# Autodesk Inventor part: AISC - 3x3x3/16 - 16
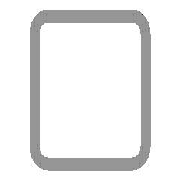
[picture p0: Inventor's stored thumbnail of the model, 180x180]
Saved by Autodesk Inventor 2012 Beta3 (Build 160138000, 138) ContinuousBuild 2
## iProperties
_CCFamilyMember: 9
_CCFamilyDisplayName: ANSI AISC (Square) - Tube
_FrameMemberDoc: Frame Member File
_Version: 15.0.0
_GetPNFromCC: 1
Created: 2010-11
Part Number: AISC - 3x3x3/16 - 16
Material: Steel, Mild
Description: Tube
Document SubType Name: Modeling
Standard: ANSI
Designer: Beta-8540w
Standards Organization: ANSI
Language: en-US
Size Designation: 3x3x3/16
Categories: <MemberInstance><Categories><Category DisplayName="Structural Shapes" InternalName="089c4875-fa83-4c05-b084-43b9cc11f5ed" Mnemonic="GRDR"><CategoryParameter Dis
Stock Number: 3x3x3/16
Density: 7.86 g/cm^3
IsCustomPart: 1
G_L: 16.000 in
G_W: 3.000 in
G_H: 3.000 in
Author: Beta-8540w
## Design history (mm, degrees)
node "Start plane"
node "End plane"
sketch "Sketch"
  geometry: L1 (-38.1, -28.575)-(-38.1, 28.575); L2 (-28.575, 38.1)-(28.575, 38.1); L3 (38.1, 28.575)-(38.1, -28.575); L4 (28.575, -38.1)-(-28.575, -38.1); L5 (-28.575, 33.337)-(28.575, 33.338); L6 (33.338, 28.575)-(33.338, -28.575); L7 (28.575, -33.337)-(-28.575, -33.338); L8 (-33.338, -28.575)-(-33.338, 28.575); L9 (0, 56.102)-(0, -56.102) reference; L10 (-56.102, 0)-(56.102, 0) reference; A1 r 9.525 centre (-28.575, -28.575) between (-38.1, -28.575) and (-28.575, -38.1); A2 r 9.525 centre (-28.575, 28.575) between (-28.575, 38.1) and (-38.1, 28.575); A3 r 9.525 centre (28.575, 28.575) between (38.1, 28.575) and (28.575, 38.1); A4 r 9.525 centre (28.575, -28.575) between (28.575, -38.1) and (38.1, -28.575); A5 r 4.763 centre (-28.575, 28.575) between (-28.575, 33.337) and (-33.338, 28.575); A6 r 4.763 centre (28.575, 28.575) between (33.338, 28.575) and (28.575, 33.338); A7 r 4.763 centre (28.575, -28.575) between (28.575, -33.337) and (33.338, -28.575); A8 r 4.763 centre (-28.575, -28.575) between (-33.338, -28.575) and (-28.575, -33.338)
  constraints: 16 end point, 16 point on circle, 8 centre point, 8 tangent, 4 parallel, 3 equal radius, 2 perpendicular, 7 other
  dimensions: "d10" = 76.2 distance between parallel lines of L2 L4 (= G_H); "d11" = 76.2 distance between parallel lines of L1 L3 (= G_W); "d12" = 4.7625 distance between parallel lines of L3 L6 (= G_T); "d15" = 38.1 distance between parallel lines of L2 L10 (= 0.5 x d10); "d16" = 38.1 distance between parallel lines of L9 L3 (= 0.5 x d11); "d17" = 9.525 radius of A1 (= G_IR)
extrude "Body" new body sketch "Sketch" stored distance "d3" = 406.4 (= G_L); taper "d4" = 0 deg
node "Driven Length"
  sketch "Sketch3"
    geometry: L1 (0, 0)-(10, 0) reference
    constraints: 2 end point, 1 horizontal
  workplane "Work Plane3"
  sketch "Sketch4"
    geometry: L1 (-2, -114.3)-(12, -114.3) reference; L2 (-2, 292.1)-(12, 292.1) reference
    dimensions: "d19" = 406.4 distance between parallel lines of L1 L2 (derived)
workplane "Work Plane4"
split "Split1"
body "Solid1"
other parameters: "G_W" = 76.2 [user parameter; used in 1 equation term], "G_H" = 76.2 [user parameter; used in 1 equation term], "G_T" = 4.7625 [user parameter; used in 1 equation term], "G_IR" = 9.525 [user parameter; used in 1 equation term], "G_L" = 406.4 (= d19) [user parameter; used in 1 equation term], "G_OFFSET_START" = 114.3 [user parameter; used in 1 equation term], "G_OFFSET_END" = 38.1 [user parameter; used in 1 equation term], "d13" = -114.3 (= -G_OFFSET_START), "d14" = 292.1 (= G_OFFSET_END + B_L), "B_L" = 254 [user parameter; used in 1 equation term], "d18" = 90 deg
